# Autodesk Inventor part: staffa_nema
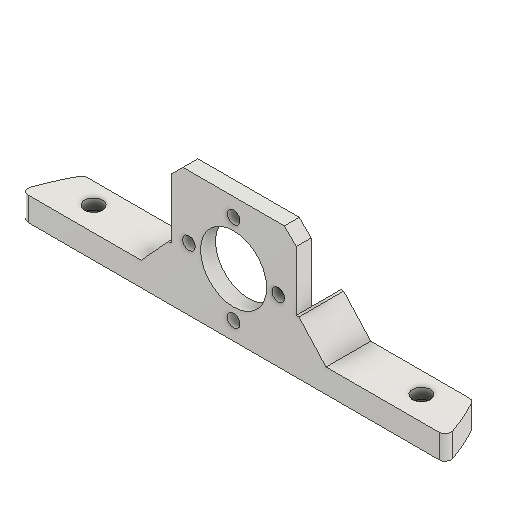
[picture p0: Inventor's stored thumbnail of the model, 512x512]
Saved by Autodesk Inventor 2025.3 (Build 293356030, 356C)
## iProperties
Created: 2026-03
Part Number: staffa_nema
Material: Plastica ABS
Document SubType Name: Modeling
Designer: R5800u
Density: 1.06 g/cm^3
Appearance: Acciaio
Author: R5800u
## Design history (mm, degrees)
sketch "Schizzo1"
  geometry: L1 (-21, 21)-(21, 21); L2 (21, 21)-(21, -21); L3 (21, -21)-(-21, -21); L4 (-21, -21)-(-21, 21); L5 (-21, 21)-(21, -21); L6 (21, 21)-(-21, -21); C1 r 11.1 at (0, 0); 1 further point
  constraints: 12 end point, 2 midpoint, 2 parallel, 1 centre point, 1 coincident, 1 horizontal, 1 perpendicular
  dimensions: "d0" = 42 distance of L2.end L3.end; "d1" = 42 distance of L1.end L2.end; "d2" = 22.2 diameter of C1
extrude "Estrusione1" new body sketch "Schizzo1" distance "d3" = 5; taper "d4" = 0 deg
sketch "Schizzo2"
  geometry: L1 (42, 0)-(42, 5) reference; L2 (52, -10)-(42, -10); L3 (42, -10)-(42, 5); L4 (-10, -10)-(0, -10); L5 (0, -10)-(0, 5); L6 (0, 5)-(42, 5) reference; L7 (42, 5)-(92.778, 5); L8 (42, 99)-(42, 64) reference; L9 (42, 64)-(82.709, 64) reference; L10 (0, -45)-(0, -10) reference; L11 (0, 5)-(-5, 5); L12 (-5, 5)-(-50.701, 5); L13 (-44.238, -10)-(0, -10) reference; L14 (0, 0)-(0, 5) reference; L15 (0.136, -0.6)-(0.136, -27) reference; L16 (42, -0.6)-(42, -27) reference; L17 (42, -10)-(86.238, -10) reference; L18 (42, 0)-(42, 5) reference; L19 (82.709, -10)-(42, -10) reference; L20 (42, -10)-(42, -45) reference; L21 (0, -10)-(-40.709, -10) reference; L22 (-40.709, 64)-(0, 64) reference; L23 (0, 64)-(0, 99) reference; C1 r 2.15 at (76, 57) reference; C2 r 2.15 at (76, -3) reference; C3 r 2.15 at (-34, 57) reference; C4 r 2.15 at (-34, -3) reference; C5 r 3.25 at (21, 27) reference; A1 r 75 centre (21, 27) between (42, 99) and (0, 99) reference; A2 r 75 centre (21, 27) between (86.238, -10) and (-44.238, -10) reference; A3 r 75 centre (21, 27) between (84.4, -13.068) and (84.4, 67.068) reference; A4 r 2 centre (82.709, 66) between (82.709, 64) and (84.4, 67.068) reference; A5 r 2 centre (82.709, -12) between (84.4, -13.068) and (82.709, -10) reference; A6 r 75 centre (21, 27) between (0, -45) and (42, -45) reference; A7 r 2 centre (-40.709, -12) between (-40.709, -10) and (-42.4, -13.068) reference; A8 r 75 centre (21, 27) between (-42.4, 67.068) and (-42.4, -13.068) reference; A9 r 2 centre (-40.709, 66) between (-42.4, 67.068) and (-40.709, 64) reference; 24 further points
  constraints: 22 end point, 3 horizontal, 2 point on circle, 2 point on line, 2 vertical, 1 centre point, 1 coincident, 10 other
extrude "Estrusione2" join sketch "Schizzo2" distance "d8" = 8; taper "d9" = 0 deg
chamfer "Smusso2" distance "d13" = 4; stored, may be unused: second distance "d14" = 2, angle "d15" = 45 deg
sketch "Schizzo3"
  geometry: L1 (21, -13)-(21, 17) reference; L2 (21, -2)-(31, -13); L3 (21, -13)-(71.701, -13) reference; L4 (21.909, -3)-(21, -3); 1 further point
  constraints: 4 end point, 4 point on line, 1 perpendicular
  dimensions: "d16" = 10 distance from line of L1 L2.end; "d17" = 11 distance of L1.start L2.start; "d20" = 1 distance from line of L4 L2.start
node "Piano di lavoro1"
extrude "Estrusione3" join sketch "Schizzo3" stored distance "d18" = 8; taper "d19" = 0 deg
mirror "Speculare1"
sketch "Schizzo4"
  geometry: C1 r 1.621 at (0, 15) reference; C2 r 1.621 at (0, -15) reference; C3 r 1.621 at (-15, 0) reference; C4 r 1.621 at (15, 0) reference; 1 further point
  constraints: 4 centre point, 8 other
hole "Foro1" sketch "Schizzo4" at (0, 15), (15, 0), (0, -15), (-15, 0) diameter "d21" = 4.3; stored, may be unused: countersink angle "d25" = 90 deg, drill point angle "d27" = 118 deg; dims "d22" = 6, "d23" = 8, "d24" = 4.6, "d26" = 8
fillet "Raccordo1" dims "d28" = 2
sketch "Schizzo5"
  geometry: L1 (23.15, -5)-(18.85, -5) reference; L2 (-47.942, -5)-(-10, -5) reference; L3 (21, -5)-(21, 19.598); 3 further points
  constraints: 2 end point, 1 midpoint, 1 symmetric about line, 1 vertical
  dimensions: "d30" = 8 distance from line of L2 point (-34, 3); "d38" = 55 distance from line of point (-34, 3) L3
hole "Foro2" sketch "Schizzo5" at (-34, 3), (76, 3) diameter "d31" = 3.2; stored, may be unused: countersink angle "d35" = 90 deg, drill point angle "d37" = 118 deg; dims "d32" = 6, "d33" = 6, "d34" = 3.5, "d36" = 8
node "Solido1"
node "Riferimento1"
